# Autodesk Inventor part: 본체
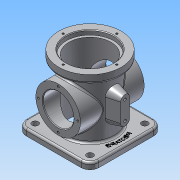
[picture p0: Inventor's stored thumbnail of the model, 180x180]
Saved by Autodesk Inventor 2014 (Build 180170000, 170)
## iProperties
Created: 2021-03
Part Number: 본체
Material: 알루미늄 6061
Document SubType Name: Modeling
Designer: net
Density: 2.71 g/cm^3
Appearance: 알루미늄 - 평지
Mass: 841.498 g
Surface Area: 865.675 cm^2
Volume: 310.516 cm^3
Author: net
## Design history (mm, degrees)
sketch "스케치2"
  geometry: C1 r 38 at (0, 0); 1 further point
  constraints: 1 centre point, 1 coincident
  dimensions: "d3" = 76 diameter of C1
extrude "돌출2" new body sketch "스케치2" stored distance "d4" = 111; taper "d5" = 0 deg
sketch "스케치3"
  geometry: C1 r 38 at (0, 0) reference; C2 r 49 at (0, 0)
  constraints: 1 centre point, 1 coincident
  dimensions: "d6" = 98 diameter of C2
extrude "돌출3" join sketch "스케치3" distance "d7" = 13; taper "d8" = 0 deg
sketch "스케치4"
  geometry: C1 r 49 at (0, 0) reference; C2 r 37 at (0, 0)
  constraints: 1 centre point, 1 coincident
  dimensions: "d9" = 74 diameter of C2
extrude "돌출4" cut sketch "스케치4" distance "d10" = 7; taper "d11" = 0 deg
sketch "스케치5"
  geometry: C1 r 37 at (0, 0) reference; C2 r 33 at (0, 0)
  constraints: 1 centre point, 1 coincident
  dimensions: "d12" = 66 diameter of C2
extrude "돌출5" cut sketch "스케치5" distance "d13" = 104; taper "d14" = 0 deg
sketch "스케치6" dims "d15" = 84
  geometry: C1 r 37 at (0, 0) reference; C2 r 49 at (0, 0) reference; 2 further points
  constraints: 2 vertical alignment, 1 coincident, 2 other
hole "구멍1" sketch "스케치6" at (0, 42) diameter "d16" = 3.242; stored, may be unused: countersink angle "d20" = 90 deg, drill point angle "d22" = 118 deg; dims "d17" = 6, "d18" = 4, "d19" = 2, "d21" = 8
node "작업 평면1"
sketch "스케치7"
  geometry: L1 (-38, -55.5)-(38, -55.5) reference; C1 r 35 at (0, -1.5); 1 further point
  constraints: 1 centre point, 1 vertical alignment
  dimensions: "d27" = 70 diameter of C1; "d96" = 54 vertical distance of L1.start C1.centre
extrude "돌출6" join sketch "스케치7" stored distance "d29" = 7; taper "d30" = 0 deg
sketch "스케치8"
  geometry: C1 r 35 at (0, 0) reference; C2 r 24 at (0, 0); 1 further point
  constraints: 1 centre point, 1 coincident
  dimensions: "d31" = 48 diameter of C2
extrude "돌출7" cut sketch "스케치8" distance "d32" = 50; taper "d33" = 0 deg
sketch "스케치9" dims "d95" = 62
  geometry: C1 r 24 at (0, 0) reference; C2 r 35 at (0, 0) reference; 2 further points
  constraints: 2 vertical alignment, 1 coincident, 2 other
hole "구멍2" sketch "스케치9" at (0, 31) diameter "d35" = 3.242; stored, may be unused: countersink angle "d39" = 90 deg, drill point angle "d41" = 118 deg; dims "d36" = 6, "d37" = 4, "d38" = 2, "d40" = 8
sketch "스케치11"
  geometry: L1 (-57, -57)-(57, -57); L2 (57, -57)-(57, 57); L3 (57, 57)-(-57, 57); L4 (-57, 57)-(-57, -57); L5 (-57, -57)-(57, 57); L6 (57, -57)-(-57, 57); C1 r 38 at (0, 0) reference
  constraints: 12 end point, 2 midpoint, 2 parallel, 1 horizontal, 1 perpendicular
  dimensions: "d48" = 114 distance of L3.end L2.end; "d49" = 114 distance of L2.end L1.end
extrude "돌출8" join sketch "스케치11" distance "d50" = 10; taper "d51" = 0 deg
fillet "모깎기1" dims "d52" = 14
sketch "스케치12"
  geometry: A1 r 14 centre (-43, 43) between (-43, 57) and (-57, 43) reference; A2 r 14 centre (-43, -43) between (-57, -43) and (-43, -57) reference; A3 r 14 centre (43, -43) between (43, -57) and (57, -43) reference; A4 r 14 centre (43, 43) between (57, 43) and (43, 57) reference; 4 further points
  constraints: 4 coincident
hole "구멍3" sketch "스케치12" at (-43, 43), (-43, -43), (43, -43), (43, 43) diameter "d53" = 10; stored, may be unused: countersink angle "d57" = 90 deg, drill point angle "d59" = 118 deg; dims "d54" = 6, "d55" = 4, "d56" = 2, "d58" = 8
fillet "모깎기2" dims "d60" = 3
fillet "모깎기3" dims "d61" = 3
chamfer "모따기1" distance "d62" = 1; stored, may be unused: second distance "d63" = 2, angle "d64" = 45 deg
fillet "모깎기4" dims "d73" = 3
node "작업 평면4"
sketch "스케치14"
  geometry: L1 (0, -14.5)-(0, 14.5); L2 (7, -14.5)-(7, 14.5); L3 (-7, 14.5)-(-7, -14.5); L4 (50.211, -48.5)-(50.211, -55.5) reference; L5 (50.211, -55.5)-(-50.211, -55.5) reference; L6 (-50.211, -55.5)-(-50.211, -48.5) reference; L7 (-43, -45.672)-(43, -45.672) reference; L8 (50.211, -48.5)-(50.211, -55.5) reference; L9 (50.211, -55.5)-(-50.211, -55.5) reference; L10 (-50.211, -55.5)-(-50.211, -48.5) reference; L11 (-43, -45.672)-(43, -45.672) reference; L12 (-50, -36.5)-(-50, 33.5) reference; L13 (50.211, -48.5)-(50.211, -55.5) reference; L14 (50.211, -55.5)-(-50.211, -55.5) reference; L15 (-50.211, -55.5)-(-50.211, -48.5) reference; L16 (-43, -45.672)-(43, -45.672) reference; L17 (50, -36.5)-(50, 33.5) reference; L18 (50, 31.121)-(50, 27.879) reference; L19 (50, 0.121)-(50, -3.121) reference; L20 (50, -30.879)-(50, -34.121) reference; L21 (50, 0.121)-(50, -3.121) reference; L22 (50, -26.5)-(50, 23.5) reference; L23 (-50, -36.5)-(-50, 33.5) reference; L24 (-50, 27.879)-(-50, 31.121) reference; L25 (-50, -3.121)-(-50, 0.121) reference; L26 (-50, -34.121)-(-50, -30.879) reference; L27 (-50, -3.121)-(-50, 0.121) reference; L28 (-50, 23.5)-(-50, -26.5) reference; L29 (50, 0.121)-(50, -3.121) reference; A1 r 7 centre (0, -14.5) between (-7, -14.5) and (7, -14.5); A2 r 7 centre (0, 14.5) between (7, 14.5) and (-7, 14.5); 5 further points
  constraints: 8 end point, 6 point on circle, 4 tangent, 3 vertical alignment, 2 centre point, 2 midpoint, 1 parallel, 1 vertical, 6 other
  dimensions: "d80" = 43 distance of point (0, -21.5) point (0, 21.5); "d82" = 14 distance between parallel lines of L2 L3; "d99" = 20 vertical distance of point (0, -21.5) point (50, -1.5)
extrude "돌출10" join sketch "스케치14" stored distance "d83" = 25; taper "d84" = 15 deg
sketch "스케치17"
  geometry: A1 r 7 centre (-14.5, 0) between (-14.5, 7) and (-14.5, -7) reference; A2 r 7 centre (14.5, 0) between (14.5, -7) and (14.5, 7) reference; 3 further points
  constraints: 2 coincident
hole "구멍4" sketch "스케치17" at (14.5, 0), (-14.5, 0) diameter "d85" = 4.134; stored, may be unused: countersink angle "d89" = 90 deg, drill point angle "d91" = 118 deg; dims "d86" = 8, "d87" = 4, "d88" = 2, "d90" = 10
sketch "스케치18"
  geometry: C1 r 41 at (0, 0) reference; C2 r 50 at (0, 0)
  constraints: 1 centre point, 1 coincident, 1 other
  dimensions: "d92" = 100 diameter of C2
feature "엠보싱1" sketch "스케치18" dims "d13" = 104, "d14" = 0, "d93" = 0.5, "d94" = 0
node "솔리드2"
pattern_circular "원형 패턴1" dims angle "d24" = 360 deg
pattern_circular "원형 패턴2" dims angle "d43" = 360 deg
mirror "대칭1"
node "투영된 루프1"
node "투영된 루프2"
node "절단 모서리 투영3"
node "절단 모서리 투영4"
node "절단 모서리 투영5"
other parameters: "d78" = 55
